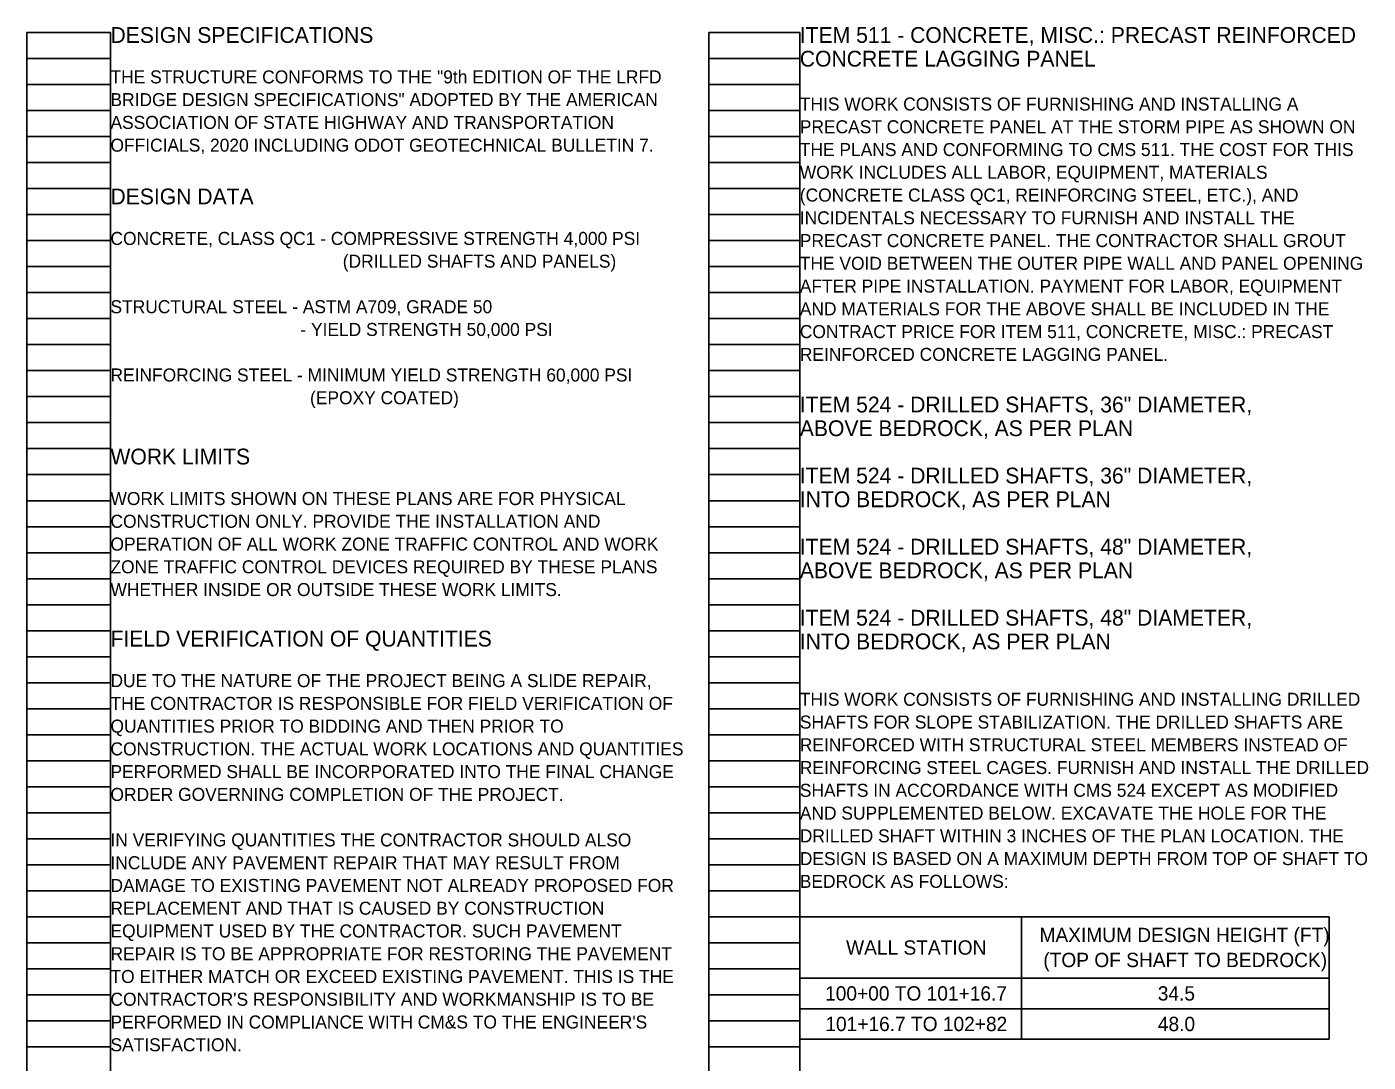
# Model space of a CAD drawing. Extents: x -2.8 to 53.9, y -6 to 15.2.
# Drawn here: x -1.29 to 13.15, y 4.08 to 15.23 of the extents above; entities that cross this region are included whole.
import ezdxf

# ---------------------------------------------------------------- set-up
doc = ezdxf.new("R2010")
doc.units = 0
doc.layers.add('SC_Scratch1', color=7, linetype='Continuous')
doc.layers.add('SH_Text', color=7, linetype='Continuous')

msp = doc.modelspace()

# ---------------------------------------------------------------- linework, layer by layer
at = {"layer": 'SC_Scratch1'}
for p, q in [((-1.287, -4.995), (-1.287, 15.165)), ((-1.287, 15.165), (-0.387, 15.165)), ((-0.387, -4.995), (-0.387, 15.165)), ((6.053, -4.995), (6.053, 15.165)), ((6.053, 15.165), (7.033, 15.165)), ((7.033, -4.995), (7.033, 15.165)), ((-1.287, 14.885), (-0.387, 14.885)), ((6.053, 14.885), (7.033, 14.885)), ((-1.287, 14.605), (-0.387, 14.605)), ((6.053, 14.605), (7.033, 14.605)), ((-1.287, 14.325), (-0.387, 14.325)), ((6.053, 14.325), (7.033, 14.325)), ((-1.287, 14.045), (-0.387, 14.045)), ((6.053, 14.045), (7.033, 14.045)), ((-1.287, 13.765), (-0.387, 13.765)), ((6.053, 13.765), (7.033, 13.765)), ((-1.287, 13.485), (-0.387, 13.485)), ((6.053, 13.485), (7.033, 13.485)), ((-1.287, 13.205), (-0.387, 13.205)), ((6.053, 13.205), (7.033, 13.205)), ((-1.287, 12.925), (-0.387, 12.925)), ((6.053, 12.925), (7.033, 12.925)), ((-1.287, 12.645), (-0.387, 12.645)), ((6.053, 12.645), (7.033, 12.645)), ((-1.287, 12.365), (-0.387, 12.365)), ((6.053, 12.365), (7.033, 12.365)), ((-1.287, 12.085), (-0.387, 12.085)), ((6.053, 12.085), (7.033, 12.085)), ((-1.287, 11.805), (-0.387, 11.805)), ((6.053, 11.805), (7.033, 11.805)), ((-1.287, 11.525), (-0.387, 11.525)), ((6.053, 11.525), (7.033, 11.525)), ((-1.287, 11.245), (-0.387, 11.245)), ((6.053, 11.245), (7.033, 11.245)), ((-1.287, 10.965), (-0.387, 10.965)), ((6.053, 10.965), (7.033, 10.965)), ((-1.287, 10.685), (-0.387, 10.685)), ((6.053, 10.685), (7.033, 10.685)), ((-1.287, 10.405), (-0.387, 10.405)), ((6.053, 10.405), (7.033, 10.405)), ((-1.287, 10.125), (-0.387, 10.125)), ((6.053, 10.125), (7.033, 10.125)), ((-1.287, 9.845), (-0.387, 9.845)), ((6.053, 9.845), (7.033, 9.845)), ((-1.287, 9.565), (-0.387, 9.565)), ((6.053, 9.565), (7.033, 9.565)), ((-1.287, 9.285), (-0.387, 9.285)), ((6.053, 9.285), (7.033, 9.285)), ((-1.287, 9.005), (-0.387, 9.005)), ((6.053, 9.005), (7.033, 9.005)), ((-1.287, 8.725), (-0.387, 8.725)), ((6.053, 8.725), (7.033, 8.725)), ((-1.287, 8.445), (-0.387, 8.445)), ((6.053, 8.445), (7.033, 8.445)), ((-1.287, 8.165), (-0.387, 8.165)), ((6.053, 8.165), (7.033, 8.165)), ((-1.287, 7.885), (-0.387, 7.885)), ((6.053, 7.885), (7.033, 7.885)), ((-1.287, 7.605), (-0.387, 7.605)), ((6.053, 7.605), (7.033, 7.605)), ((-1.287, 7.325), (-0.387, 7.325)), ((6.053, 7.325), (7.033, 7.325)), ((-1.287, 7.045), (-0.387, 7.045)), ((6.053, 7.045), (7.033, 7.045)), ((-1.287, 6.765), (-0.387, 6.765)), ((6.053, 6.765), (7.033, 6.765)), ((-1.287, 6.485), (-0.387, 6.485)), ((6.053, 6.485), (7.033, 6.485)), ((-1.287, 6.205), (-0.387, 6.205)), ((6.053, 6.205), (7.033, 6.205)), ((-1.287, 5.925), (-0.387, 5.925)), ((6.053, 5.925), (7.033, 5.925)), ((-1.287, 5.645), (-0.387, 5.645)), ((6.053, 5.645), (7.033, 5.645)), ((-1.287, 5.365), (-0.387, 5.365)), ((6.053, 5.365), (7.033, 5.365)), ((-1.287, 5.085), (-0.387, 5.085)), ((6.053, 5.085), (7.033, 5.085)), ((-1.287, 4.805), (-0.387, 4.805)), ((6.053, 4.805), (7.033, 4.805)), ((-1.287, 4.525), (-0.387, 4.525)), ((6.053, 4.525), (7.033, 4.525)), ((-1.287, 4.245), (-0.387, 4.245)), ((6.053, 4.245), (7.033, 4.245))]:
    msp.add_line(p, q, dxfattribs=at)
at = {"layer": 'SH_Text'}
for p, q in [((7.033, 5.645), (12.732, 5.645)), ((7.033, 5.645), (7.033, 4.327)), ((9.421, 5.645), (9.421, 4.327)), ((12.732, 5.645), (12.732, 4.327)), ((7.033, 4.986), (12.732, 4.986)), ((7.033, 4.656), (12.732, 4.656)), ((7.033, 4.327), (12.732, 4.327))]:
    msp.add_line(p, q, dxfattribs=at)

# ---------------------------------------------------------------- texts
for s, height, p in [('DESIGN SPECIFICATIONS', 0.17, (-0.387, 15.053)), ('ITEM 511 - CONCRETE, MISC.: PRECAST REINFORCED ', 0.17, (7.033, 15.053)), ('CONCRETE LAGGING PANEL', 0.17, (7.033, 14.798)), ('THE STRUCTURE CONFORMS TO THE "9th EDITION OF THE LRFD ', 0.14, (-0.387, 14.617)), ('BRIDGE DESIGN SPECIFICATIONS" ADOPTED BY THE AMERICAN ', 0.14, (-0.387, 14.372)), ('THIS WORK CONSISTS OF FURNISHING AND INSTALLING A ', 0.14, (7.033, 14.325)), ('ASSOCIATION OF STATE HIGHWAY AND TRANSPORTATION ', 0.14, (-0.387, 14.127)), ('PRECAST CONCRETE PANEL AT THE STORM PIPE AS SHOWN ON ', 0.14, (7.033, 14.08)), ('OFFICIALS, 2020 INCLUDING ODOT GEOTECHNICAL BULLETIN 7.', 0.14, (-0.387, 13.882)), ('THE PLANS AND CONFORMING TO CMS 511. THE COST FOR THIS ', 0.14, (7.033, 13.835)), ('WORK INCLUDES ALL LABOR, EQUIPMENT, MATERIALS ', 0.14, (7.033, 13.59)), ('DESIGN DATA', 0.17, (-0.387, 13.315)), ('(CONCRETE CLASS QC1, REINFORCING STEEL, ETC.), AND ', 0.14, (7.033, 13.345)), ('INCIDENTALS NECESSARY TO FURNISH AND INSTALL THE ', 0.14, (7.033, 13.1)), ('CONCRETE, CLASS QC1 - COMPRESSIVE STRENGTH 4,000 PSI', 0.14, (-0.387, 12.878)), ('PRECAST CONCRETE PANEL. THE CONTRACTOR SHALL GROUT ', 0.14, (7.033, 12.855)), ('     (DRILLED SHAFTS AND PANELS)', 0.14, (1.853, 12.633)), ('THE VOID BETWEEN THE OUTER PIPE WALL AND PANEL OPENING ', 0.14, (7.033, 12.61)), ('AFTER PIPE INSTALLATION. PAYMENT FOR LABOR, EQUIPMENT ', 0.14, (7.033, 12.365)), ('STRUCTURAL STEEL - ASTM A709, GRADE 50 ', 0.14, (-0.387, 12.143)), ('AND MATERIALS FOR THE ABOVE SHALL BE INCLUDED IN THE ', 0.14, (7.033, 12.12)), ('       - YIELD STRENGTH 50,000 PSI', 0.14, (1.293, 11.898)), ('CONTRACT PRICE FOR ITEM 511, CONCRETE, MISC.: PRECAST ', 0.14, (7.033, 11.875)), ('REINFORCED CONCRETE LAGGING PANEL.', 0.14, (7.033, 11.63)), ('REINFORCING STEEL - MINIMUM YIELD STRENGTH 60,000 PSI', 0.14, (-0.387, 11.408)), ('         (EPOXY COATED)', 0.14, (1.293, 11.163)), ('ITEM 524 - DRILLED SHAFTS, 36" DIAMETER, ', 0.17, (7.033, 11.075)), ('ABOVE BEDROCK, AS PER PLAN', 0.17, (7.033, 10.82)), ('WORK LIMITS', 0.17, (-0.387, 10.515)), ('ITEM 524 - DRILLED SHAFTS, 36" DIAMETER, ', 0.17, (7.033, 10.31)), ('WORK LIMITS SHOWN ON THESE PLANS ARE FOR PHYSICAL ', 0.14, (-0.387, 10.078)), ('INTO BEDROCK, AS PER PLAN', 0.17, (7.033, 10.055)), ('CONSTRUCTION ONLY. PROVIDE THE INSTALLATION AND ', 0.14, (-0.387, 9.833)), ('OPERATION OF ALL WORK ZONE TRAFFIC CONTROL AND WORK ', 0.14, (-0.387, 9.588)), ('ITEM 524 - DRILLED SHAFTS, 48" DIAMETER, ', 0.17, (7.033, 9.545)), ('ZONE TRAFFIC CONTROL DEVICES REQUIRED BY THESE PLANS ', 0.14, (-0.387, 9.343)), ('ABOVE BEDROCK, AS PER PLAN', 0.17, (7.033, 9.29)), ('WHETHER INSIDE OR OUTSIDE THESE WORK LIMITS.', 0.14, (-0.387, 9.098)), ('ITEM 524 - DRILLED SHAFTS, 48" DIAMETER, ', 0.17, (7.033, 8.78)), ('FIELD VERIFICATION OF QUANTITIES', 0.17, (-0.387, 8.555)), ('INTO BEDROCK, AS PER PLAN', 0.17, (7.033, 8.525)), ('DUE TO THE NATURE OF THE PROJECT BEING A SLIDE REPAIR, ', 0.14, (-0.387, 8.118)), ('THE CONTRACTOR IS RESPONSIBLE FOR FIELD VERIFICATION OF ', 0.14, (-0.387, 7.873)), ('THIS WORK CONSISTS OF FURNISHING AND INSTALLING DRILLED ', 0.14, (7.033, 7.917)), ('SHAFTS FOR SLOPE STABILIZATION. THE DRILLED SHAFTS ARE ', 0.14, (7.033, 7.672)), ('QUANTITIES PRIOR TO BIDDING AND THEN PRIOR TO ', 0.14, (-0.387, 7.628)), ('CONSTRUCTION. THE ACTUAL WORK LOCATIONS AND QUANTITIES ', 0.14, (-0.387, 7.383)), ('REINFORCED WITH STRUCTURAL STEEL MEMBERS INSTEAD OF ', 0.14, (7.033, 7.427)), ('PERFORMED SHALL BE INCORPORATED INTO THE FINAL CHANGE ', 0.14, (-0.387, 7.138)), ('REINFORCING STEEL CAGES. FURNISH AND INSTALL THE DRILLED ', 0.14, (7.033, 7.182)), ('SHAFTS IN ACCORDANCE WITH CMS 524 EXCEPT AS MODIFIED ', 0.14, (7.033, 6.937)), ('ORDER GOVERNING COMPLETION OF THE PROJECT.', 0.14, (-0.387, 6.893)), ('AND SUPPLEMENTED BELOW. EXCAVATE THE HOLE FOR THE ', 0.14, (7.033, 6.692)), ('IN VERIFYING QUANTITIES THE CONTRACTOR SHOULD ALSO ', 0.14, (-0.387, 6.403)), ('DRILLED SHAFT WITHIN 3 INCHES OF THE PLAN LOCATION. THE ', 0.14, (7.033, 6.447)), ('INCLUDE ANY PAVEMENT REPAIR THAT MAY RESULT FROM ', 0.14, (-0.387, 6.158)), ('DESIGN IS BASED ON A MAXIMUM DEPTH FROM TOP OF SHAFT TO ', 0.14, (7.033, 6.202)), ('BEDROCK AS FOLLOWS:', 0.14, (7.033, 5.957)), ('DAMAGE TO EXISTING PAVEMENT NOT ALREADY PROPOSED FOR ', 0.14, (-0.387, 5.913)), ('REPLACEMENT AND THAT IS CAUSED BY CONSTRUCTION ', 0.14, (-0.387, 5.668)), ('EQUIPMENT USED BY THE CONTRACTOR. SUCH PAVEMENT ', 0.14, (-0.387, 5.423)), ('MAXIMUM DESIGN HEIGHT (FT) ', 0.154, (9.613, 5.373)), ('WALL STATION', 0.154, (7.531, 5.238)), ('REPAIR IS TO BE APPROPRIATE FOR RESTORING THE PAVEMENT ', 0.14, (-0.387, 5.178)), ('(TOP OF SHAFT TO BEDROCK)', 0.154, (9.654, 5.104)), ('TO EITHER MATCH OR EXCEED EXISTING PAVEMENT. THIS IS THE ', 0.14, (-0.387, 4.933)), ("CONTRACTOR'S RESPONSIBILITY AND WORKMANSHIP IS TO BE ", 0.14, (-0.387, 4.688)), ('100+00 TO 101+16.7', 0.154, (7.305, 4.744)), ('34.5', 0.154, (10.886, 4.744)), ("PERFORMED IN COMPLIANCE WITH CM&S TO THE ENGINEER'S ", 0.14, (-0.387, 4.443)), ('101+16.7 TO 102+82', 0.154, (7.308, 4.415)), ('48.0', 0.154, (10.887, 4.415)), ('SATISFACTION.', 0.14, (-0.387, 4.198))]:
    msp.add_text(s, height=height, dxfattribs=at).set_placement(p)

doc.saveas('drawing.dxf')
